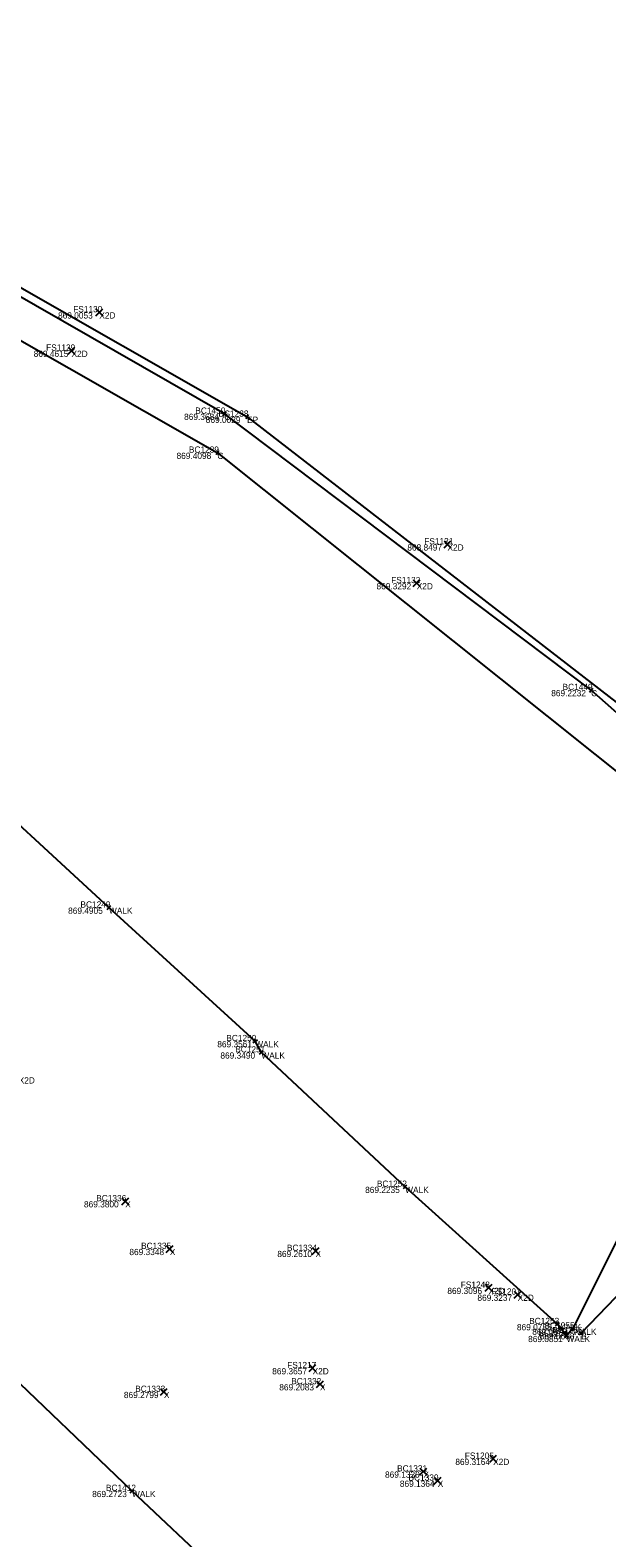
# Model space of a CAD drawing. Extents: x 1479425 to 1480294, y 379351 to 380102.
# Drawn here: x 1479647.93 to 1479653.49, y 379862.2 to 379876.74 of the extents above; entities that cross this region are included whole.
import ezdxf

# ---------------------------------------------------------------- set-up
doc = ezdxf.new("R2010")
doc.units = 0
for name, color, linetype in [('PV_X_Curb', 7, 'Continuous'), ('PV_X_Walk', 7, 'Continuous'), ('SV_X_Break_Lines', 7, 'Continuous'), ('SV_X_Random_Point', 7, 'Continuous'), ('SV_X_Shot_Marker', 7, 'Continuous'), ('SV_X_Text_Comment', 7, 'Continuous'), ('SV_X_Text_Elevation', 7, 'Continuous'), ('SV_X_Text_Name', 7, 'Continuous')]:
    doc.layers.add(name, color=color, linetype=linetype)

msp = doc.modelspace()

# ---------------------------------------------------------------- linework, layer by layer
at = {"layer": 'PV_X_Curb'}
for points in [[(1479674.4, 379850.809), (1479663.165, 379861.262), (1479660.481, 379863.897), (1479660.342, 379864.005), (1479659.476, 379864.862), (1479657.973, 379866.276), (1479656.299, 379867.861), (1479655.478, 379868.485), (1479655.394, 379868.553), (1479653.34, 379870.372), (1479649.803, 379873.037), (1479644.836, 379875.882), (1479640.971, 379876.984), (1479637.732, 379877.688), (1479634.889, 379878.057), (1479629.551, 379877.977), (1479626.942, 379877.55), (1479624.927, 379877.231), (1479623.22, 379876.871), (1479619.552, 379875.996), (1479615.007, 379874.797)], [(1479644.718, 379876.034), (1479650.021, 379873.008), (1479655.529, 379868.745), (1479656.43, 379867.829), (1479659.466, 379865.051), (1479660.571, 379864.006), (1479667.529, 379857.521), (1479674.55, 379850.816), (1479681.356, 379844.557), (1479695.384, 379831.416), (1479709.512, 379818.131), (1479724.003, 379804.728), (1479730.662, 379798.272), (1479750.68, 379779.69), (1479759.253, 379771.893), (1479760.555, 379770.78), (1479775.03, 379758.526), (1479788.183, 379747.585), (1479800.537, 379737.251), (1479801.677, 379736.292)], [(1479644.541, 379875.624), (1479649.735, 379872.661), (1479655.157, 379868.33), (1479655.241, 379868.295), (1479655.912, 379867.604), (1479656.298, 379867.29), (1479657.669, 379865.865), (1479659.13, 379864.497), (1479660.094, 379863.651), (1479660.221, 379863.658), (1479667.239, 379857.122), (1479681.024, 379844.208), (1479695.135, 379830.978), (1479709.331, 379817.708), (1479723.729, 379804.193), (1479729.719, 379798.6), (1479748.963, 379780.548), (1479759.065, 379771.485), (1479760.185, 379770.473), (1479774.837, 379758.13), (1479787.835, 379747.16), (1479799.962, 379737.109), (1479801.3, 379736.045)]]:
    msp.add_lwpolyline(points, dxfattribs=at)
at = {"layer": 'PV_X_Walk'}
for points in [[(1479656.441, 379861.306), (1479658.174, 379862.424), (1479658.221, 379862.502), (1479660.038, 379863.536), (1479659.044, 379864.438), (1479657.659, 379863.042), (1479657.584, 379862.997), (1479656.161, 379864.36), (1479654.75, 379865.767), (1479654.8, 379865.836), (1479656.102, 379867.216), (1479655.836, 379867.458), (1479655.182, 379868.167), (1479654.209, 379866.326), (1479654.172, 379866.234), (1479653.164, 379864.213), (1479653.102, 379864.143), (1479653.016, 379864.257), (1479651.546, 379865.581), (1479650.159, 379866.877), (1479650.1, 379866.986), (1479648.689, 379868.274), (1479647.143, 379869.696)], [(1479767.055, 379754.294), (1479759.061, 379761.026), (1479757.309, 379762.481), (1479754.256, 379765.105), (1479744.261, 379773.561), (1479732.859, 379783.688), (1479719.35, 379796.384), (1479703.027, 379811.462), (1479682.443, 379830.686), (1479658.561, 379853.284), (1479656.939, 379854.798), (1479656.861, 379854.894), (1479655.393, 379856.366), (1479653.492, 379858.212), (1479653.367, 379858.315), (1479652, 379859.64), (1479651.855, 379859.767), (1479650.377, 379861.206), (1479650.331, 379861.31), (1479648.911, 379862.648), (1479647.478, 379864.017)]]:
    msp.add_lwpolyline(points, dxfattribs=at)
at = {"layer": 'SV_X_Break_Lines'}
msp.add_lwpolyline([(1479653.243, 379864.17), (1479654.741, 379865.725), (1479654.729, 379865.778), (1479656.089, 379867.212)], dxfattribs=at)
at = {"layer": 'SV_X_Random_Point'}
for p, q in [((1479648.563, 379873.982), (1479648.629, 379874.048)), ((1479648.563, 379874.048), (1479648.629, 379873.982)), ((1479648.295, 379873.611), (1479648.361, 379873.678)), ((1479648.295, 379873.678), (1479648.361, 379873.611)), ((1479651.921, 379871.744), (1479651.987, 379871.811)), ((1479651.921, 379871.811), (1479651.987, 379871.744)), ((1479651.624, 379871.37), (1479651.69, 379871.436)), ((1479651.624, 379871.436), (1479651.69, 379871.37)), ((1479648.813, 379865.408), (1479648.88, 379865.475)), ((1479648.813, 379865.475), (1479648.88, 379865.408)), ((1479649.242, 379864.948), (1479649.309, 379865.015)), ((1479649.242, 379865.015), (1479649.309, 379864.948)), ((1479650.648, 379864.929), (1479650.715, 379864.996)), ((1479650.648, 379864.996), (1479650.715, 379864.929)), ((1479652.318, 379864.574), (1479652.384, 379864.641)), ((1479652.318, 379864.641), (1479652.384, 379864.574)), ((1479652.598, 379864.508), (1479652.664, 379864.575)), ((1479652.598, 379864.575), (1479652.664, 379864.508)), ((1479650.62, 379863.799), (1479650.686, 379863.866)), ((1479650.62, 379863.866), (1479650.686, 379863.799)), ((1479649.186, 379863.57), (1479649.252, 379863.637)), ((1479649.186, 379863.637), (1479649.252, 379863.57)), ((1479650.69, 379863.644), (1479650.757, 379863.71)), ((1479650.69, 379863.71), (1479650.757, 379863.644)), ((1479651.689, 379862.802), (1479651.755, 379862.868)), ((1479651.689, 379862.868), (1479651.755, 379862.802)), ((1479652.362, 379862.925), (1479652.428, 379862.992)), ((1479652.362, 379862.992), (1479652.428, 379862.925)), ((1479651.827, 379862.713), (1479651.893, 379862.78)), ((1479651.827, 379862.78), (1479651.893, 379862.713))]:
    msp.add_line(p, q, dxfattribs=at)
at = {"layer": 'SV_X_Shot_Marker'}
for p, q in [((1479649.823, 379873.022), (1479649.783, 379873.052)), ((1479649.788, 379873.017), (1479649.818, 379873.057)), ((1479649.803, 379873.037), (1479649.803, 379873.037)), ((1479649.999, 379873.021), (1479650.042, 379872.996)), ((1479650.033, 379873.03), (1479650.008, 379872.986)), ((1479650.021, 379873.008), (1479650.021, 379873.008)), ((1479649.713, 379872.674), (1479649.757, 379872.649)), ((1479649.747, 379872.683), (1479649.723, 379872.64)), ((1479649.735, 379872.661), (1479649.735, 379872.661)), ((1479653.359, 379870.355), (1479653.322, 379870.388)), ((1479653.324, 379870.353), (1479653.357, 379870.391)), ((1479653.34, 379870.372), (1479653.34, 379870.372)), ((1479648.707, 379868.257), (1479648.671, 379868.291)), ((1479648.672, 379868.256), (1479648.706, 379868.293)), ((1479648.689, 379868.274), (1479648.689, 379868.274)), ((1479650.078, 379866.974), (1479650.122, 379866.998)), ((1479650.112, 379866.964), (1479650.089, 379867.008)), ((1479650.1, 379866.986), (1479650.1, 379866.986)), ((1479650.177, 379866.86), (1479650.14, 379866.894)), ((1479650.142, 379866.859), (1479650.176, 379866.895)), ((1479650.159, 379866.877), (1479650.159, 379866.877)), ((1479651.565, 379865.564), (1479651.528, 379865.598)), ((1479651.53, 379865.563), (1479651.563, 379865.6)), ((1479651.546, 379865.581), (1479651.546, 379865.581)), ((1479652.996, 379864.241), (1479653.036, 379864.272)), ((1479653.031, 379864.237), (1479653.001, 379864.277)), ((1479653.016, 379864.257), (1479653.016, 379864.257)), ((1479653.186, 379864.201), (1479653.142, 379864.224)), ((1479653.175, 379864.235), (1479653.153, 379864.19)), ((1479653.164, 379864.213), (1479653.164, 379864.213)), ((1479653.225, 379864.188), (1479653.261, 379864.153)), ((1479653.226, 379864.152), (1479653.261, 379864.188)), ((1479653.243, 379864.17), (1479653.243, 379864.17)), ((1479653.121, 379864.126), (1479653.084, 379864.16)), ((1479653.119, 379864.162), (1479653.086, 379864.124)), ((1479653.102, 379864.143), (1479653.102, 379864.143)), ((1479648.929, 379862.631), (1479648.893, 379862.665)), ((1479648.894, 379862.63), (1479648.928, 379862.666)), ((1479648.911, 379862.648), (1479648.911, 379862.648))]:
    msp.add_line(p, q, dxfattribs=at)

# ---------------------------------------------------------------- texts
at = {"layer": 'SV_X_Text_Comment'}
for s, p in [('X2D', (1479648.596, 379873.955)), ('X2D', (1479648.328, 379873.585)), ('C', (1479649.803, 379872.977)), ('EP', (1479650.021, 379872.948)), ('C', (1479649.735, 379872.601)), ('X2D', (1479651.954, 379871.717)), ('X2D', (1479651.657, 379871.343)), ('C', (1479653.34, 379870.312)), ('WALK', (1479648.689, 379868.214)), ('WALK', (1479650.1, 379866.926)), ('WALK', (1479650.159, 379866.817)), ('X2D', (1479647.818, 379866.577)), ('WALK', (1479651.546, 379865.521)), ('X', (1479648.846, 379865.382)), ('X', (1479649.276, 379864.922)), ('X', (1479650.681, 379864.903)), ('X2D', (1479652.351, 379864.547)), ('X2D', (1479652.631, 379864.481)), ('WALK', (1479653.016, 379864.197)), ('WALK', (1479653.164, 379864.153)), ('B', (1479653.243, 379864.11)), ('WALK', (1479653.102, 379864.083)), ('X2D', (1479650.653, 379863.772)), ('X', (1479649.219, 379863.543)), ('X', (1479650.724, 379863.617)), ('X2D', (1479652.395, 379862.898)), ('X', (1479651.722, 379862.775)), ('X', (1479651.86, 379862.687)), ('WALK', (1479648.911, 379862.588))]:
    msp.add_text(s, height=0.06, dxfattribs=at).set_placement(p)
at = {"layer": 'SV_X_Text_Elevation'}
for s, p in [('869.0053', (1479648.198, 379873.955)), ('869.4615', (1479647.963, 379873.585)), ('869.3684', (1479649.414, 379872.977)), ('869.0029', (1479649.623, 379872.948)), ('869.4098', (1479649.341, 379872.601)), ('868.8497', (1479651.567, 379871.717)), ('869.3292', (1479651.27, 379871.343)), ('869.2232', (1479652.955, 379870.312)), ('869.4905', (1479648.295, 379868.214)), ('869.3561', (1479649.734, 379866.926)), ('869.3490', (1479649.764, 379866.817)), ('869.2235', (1479651.16, 379865.521)), ('869.3800', (1479648.448, 379865.382)), ('869.3348', (1479648.886, 379864.922)), ('869.2610', (1479650.313, 379864.903)), ('869.3096', (1479651.953, 379864.547)), ('869.3237', (1479652.243, 379864.481)), ('869.0785', (1479652.624, 379864.197)), ('869.0875', (1479652.772, 379864.153)), ('869.0608', (1479652.844, 379864.11)), ('869.0851', (1479652.732, 379864.083)), ('869.3657', (1479650.264, 379863.772)), ('869.2799', (1479648.833, 379863.543)), ('869.2083', (1479650.332, 379863.617)), ('869.3164', (1479652.03, 379862.898)), ('869.1330', (1479651.352, 379862.775)), ('869.1364', (1479651.495, 379862.687)), ('869.2723', (1479648.527, 379862.588))]:
    msp.add_text(s, height=0.06, dxfattribs=at).set_placement(p)
at = {"layer": 'SV_X_Text_Name'}
for s, p in [('FS1130', (1479648.344, 379874.015)), ('FS1129', (1479648.083, 379873.645)), ('BC1450', (1479649.522, 379873.037)), ('BC1238', (1479649.745, 379873.008)), ('BC1239', (1479649.46, 379872.661)), ('FS1131', (1479651.73, 379871.777)), ('FS1132', (1479651.411, 379871.403)), ('BC1449', (1479653.064, 379870.372)), ('BC1249', (1479648.414, 379868.274)), ('BC1250', (1479649.821, 379866.986)), ('BC1251', (1479649.907, 379866.877)), ('BC1252', (1479651.273, 379865.581)), ('BC1336', (1479648.566, 379865.442)), ('BC1335', (1479648.999, 379864.982)), ('BC1334', (1479650.405, 379864.963)), ('FS1248', (1479652.082, 379864.607)), ('FS1201', (1479652.38, 379864.541)), ('BC1253', (1479652.742, 379864.257)), ('BC1254', (1479652.829, 379864.143)), ('BC1255', (1479652.89, 379864.213)), ('BC1256', (1479652.966, 379864.17)), ('FS1217', (1479650.408, 379863.832)), ('BC1332', (1479650.447, 379863.677)), ('BC1333', (1479648.942, 379863.603)), ('FS1205', (1479652.121, 379862.958)), ('BC1331', (1479651.468, 379862.835)), ('BC1330', (1479651.578, 379862.747)), ('BC1412', (1479648.66, 379862.648))]:
    msp.add_text(s, height=0.06, dxfattribs=at).set_placement(p)

doc.saveas('drawing.dxf')
